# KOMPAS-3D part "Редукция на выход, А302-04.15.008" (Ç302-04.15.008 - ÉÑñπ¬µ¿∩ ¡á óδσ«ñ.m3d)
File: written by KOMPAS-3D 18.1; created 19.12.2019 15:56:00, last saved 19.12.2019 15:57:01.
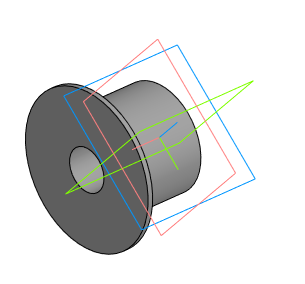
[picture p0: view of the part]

Document properties: Полное имя файла: D:\Мембранные насосы\Мембранный электропривод\А302-00.00.000 - ASTRA-302 (МЭ200)\А302-04.00.000 - Мембранный насос ASTRA-302-PP\А302-04.15.008 - Редукция на выход.m3d

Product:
- Part/product: Редукция на выход  | designation А302-04.15.008
    Материал: Полипропилен  ГОСТ 26996-86 (density 900 kg/m3)
    Масса: 0.0302348

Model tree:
1. Эскиз:1
2. Элемент вращения:1  (labels: Полипропилен  ГОСТ 26996-86)
     Угол 1 = 360

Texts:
  Линейный размер с обрывом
